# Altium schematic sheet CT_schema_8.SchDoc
size 371 x 336 mm
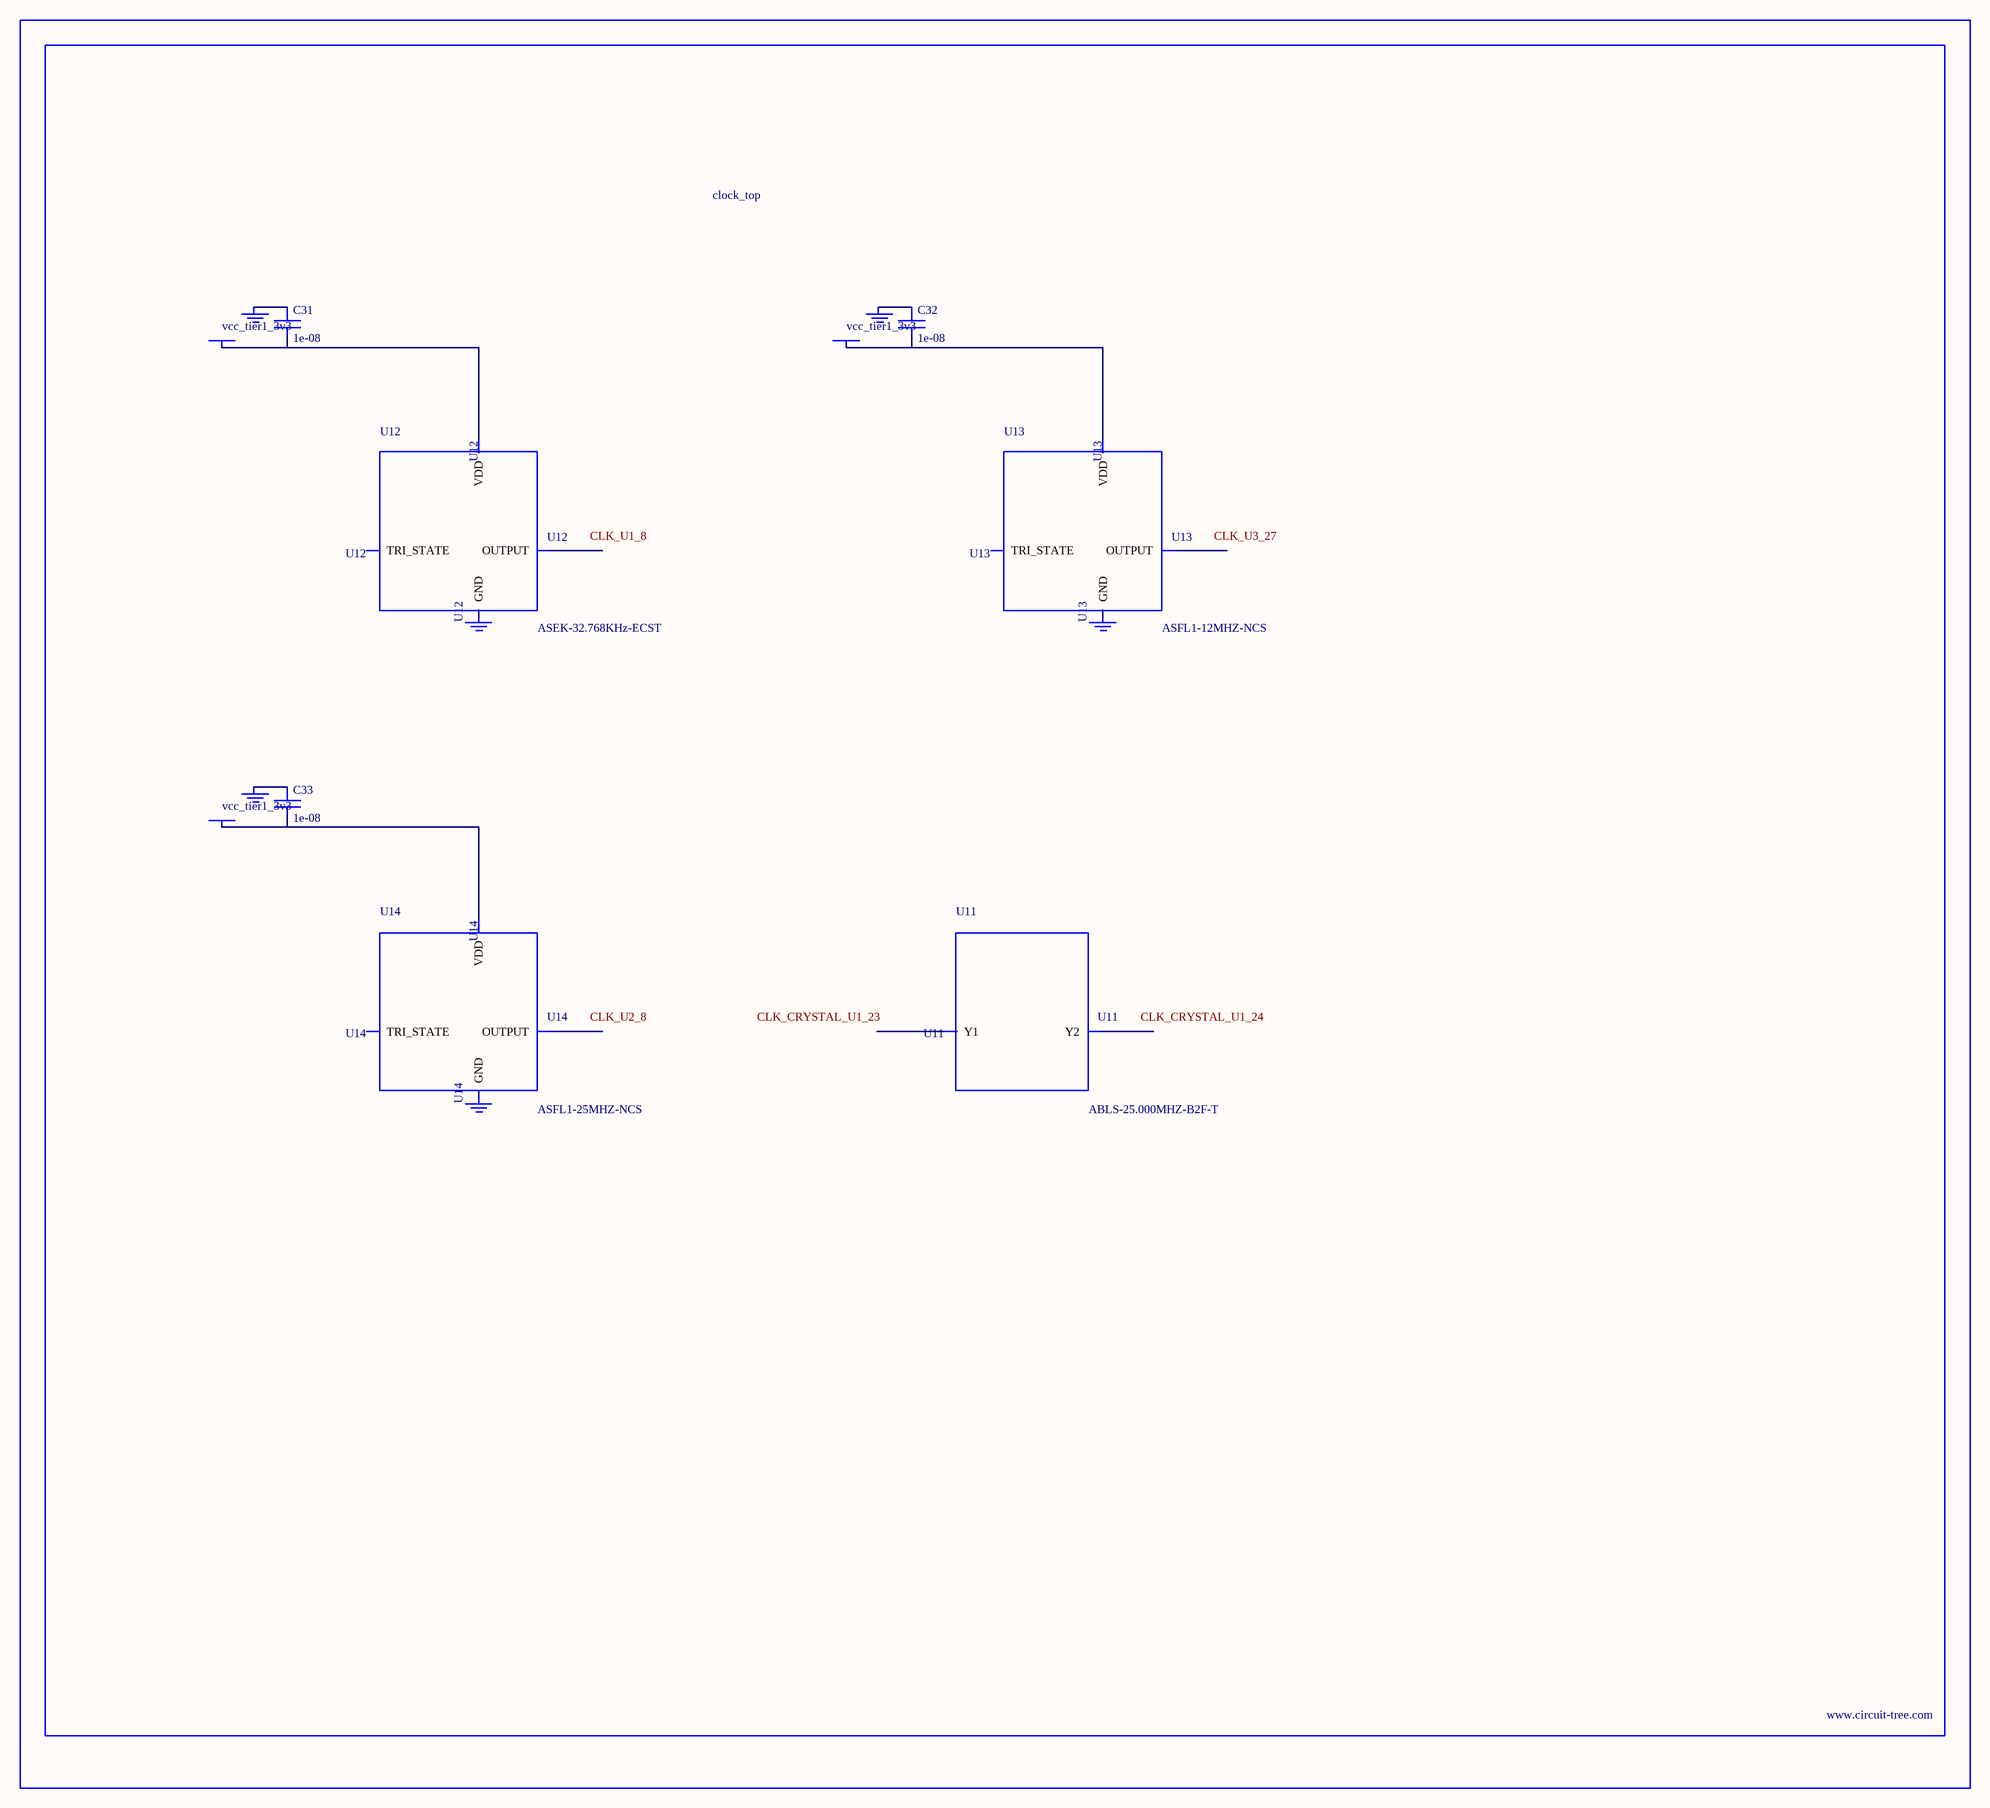
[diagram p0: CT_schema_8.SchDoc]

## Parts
BORDER7  (no value)
C31  1e-08  [C0402]
C32  1e-08  [C0402]
C33  1e-08  [C0402]
GND_INSTANCE_7_0  (no value)
GND_INSTANCE_7_1  (no value)
GND_INSTANCE_7_2  (no value)
GND_INSTANCE_7_3  (no value)
GND_INSTANCE_7_4  (no value)
GND_INSTANCE_7_5  (no value)
POWER_INSTANCE_7_0  vcc_tier1_3v3
POWER_INSTANCE_7_1  vcc_tier1_3v3
POWER_INSTANCE_7_2  vcc_tier1_3v3
U11  ABLS-25.000MHZ-B2F-T  [ABLS-25.000MHZ-B2F-T]
U12  ASEK-32.768KHz-ECST  [ASEK]
U13  ASFL1-12MHZ-NCS  [ASFL1]
U14  ASFL1-25MHZ-NCS  [ASFL1]

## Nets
NetC31_1: C31.1 GND_INSTANCE_7_0.0(GND)
NetC31_2: C31.2 POWER_INSTANCE_7_0.0(PWR) U12.4(VDD)
NetC32_1: C32.1 GND_INSTANCE_7_2.0(GND)
NetC32_2: C32.2 POWER_INSTANCE_7_1.0(PWR) U13.4(VDD)
NetC33_1: C33.1 GND_INSTANCE_7_4.0(GND)
NetC33_2: C33.2 POWER_INSTANCE_7_2.0(PWR) U14.4(VDD)

Not connected (* = marked no-connect by the designer): GND_INSTANCE_7_1 0(GND); GND_INSTANCE_7_3 0(GND); GND_INSTANCE_7_5 0(GND); U11 1(Y1) 2(Y2); U12 1(TRI_STATE) 2(GND) 3(OUTPUT); U13 1(TRI_STATE) 2(GND) 3(OUTPUT); U14 1(TRI_STATE) 2(GND) 3(OUTPUT)

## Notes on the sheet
- Labels drawn without touching a wire or pin: CLK_CRYSTAL_U1_23, CLK_CRYSTAL_U1_24, CLK_U1_8, CLK_U2_8, CLK_U3_27

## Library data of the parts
BORDER7 = BORDER_PAGE7
C31-C33 = C0402C103K3RAC
GND_INSTANCE_7_0-GND_INSTANCE_7_5 = GND
POWER_INSTANCE_7_0-POWER_INSTANCE_7_2 = PWR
